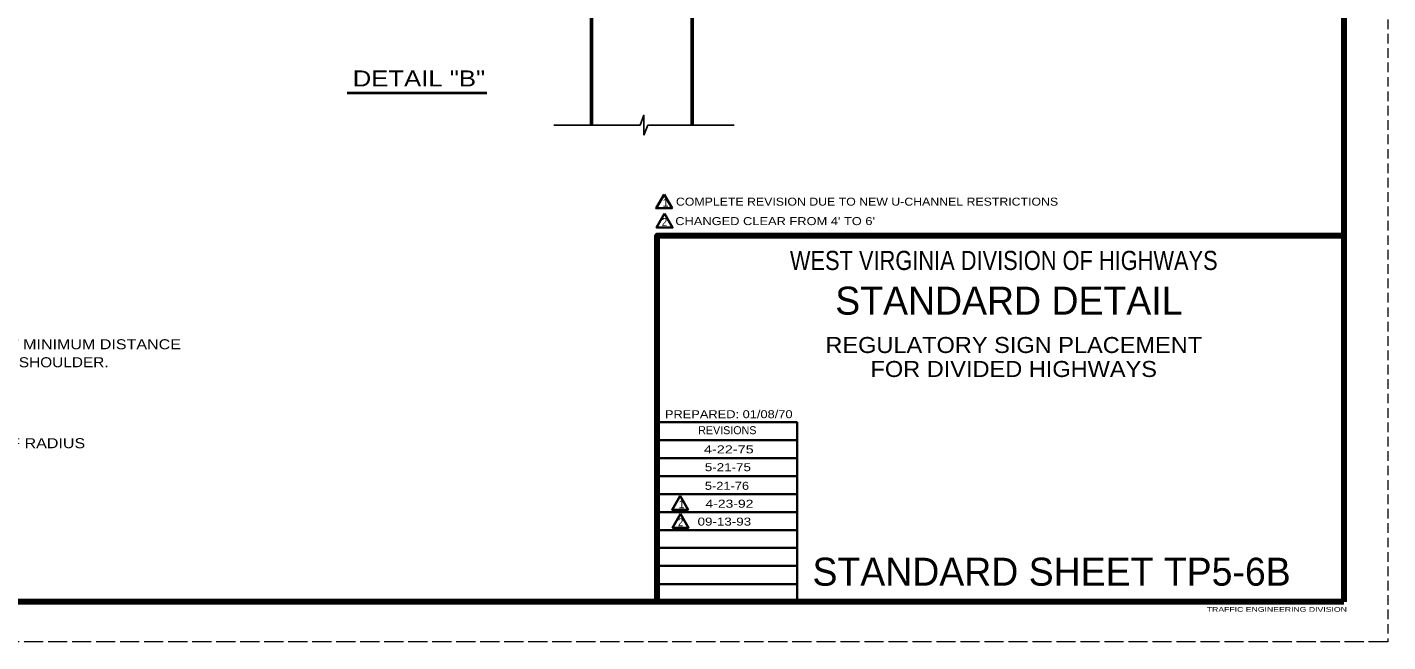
# Model space of a CAD drawing. Extents: x -133 to 547, y -328 to 112.
# Drawn here: x 206.7 to 546.7, y -328.3 to -174.6 of the extents above; entities that cross this region are included whole.
import ezdxf
from ezdxf.enums import TextEntityAlignment as Align

# ---------------------------------------------------------------- set-up
doc = ezdxf.new("R2010")
doc.units = 0
doc.header["$LTSCALE"] = 0.8
doc.linetypes.add('LONG_DASHED', pattern=[7.5, 6, -1.5])
doc.linetypes.add('MEDIUM_DASHED', pattern=[4.5, 3, -1.5])
doc.layers.add('1', color=7, linetype='Continuous', lineweight=35)
doc.layers.add('61', color=7, linetype='Continuous', lineweight=35)

msp = doc.modelspace()

# ---------------------------------------------------------------- linework, layer by layer
at = {"layer": '1', "linetype": 'MEDIUM_DASHED', "lineweight": 13}
msp.add_line((546.7136, 111.6965), (546.6936, -328.3235), dxfattribs=at)
at = {"layer": '1', "lineweight": 53}
for p, q in [((347.706, -169.145), (347.706, -199.145)), ((372.8289, -169.145), (372.8289, -199.145))]:
    msp.add_line(p, q, dxfattribs=at)
at = {"layer": '1', "lineweight": 40}
msp.add_line((286.6002, -191.0708), (321.5631, -191.0708), dxfattribs=at)
at = {"layer": '1', "lineweight": 25}
for p, q in [((338.2566, -199.1594), (359.8785, -199.1594)), ((361.7577, -199.1594), (360.8181, -201.6594)), ((361.7577, -199.1594), (383.3795, -199.1594))]:
    msp.add_line(p, q, dxfattribs=at)
at = {"layer": '1'}
for p, q in [((399.0936, -277.9035), (364.1136, -277.9035)), ((399.0936, -282.4035), (364.1136, -282.4035)), ((399.0936, -286.9035), (364.1136, -286.9035)), ((399.0936, -291.4235), (364.1136, -291.4235)), ((399.0936, -295.9035), (364.1136, -295.9035)), ((399.0936, -300.3835), (364.1136, -300.3835)), ((399.0936, -304.8835), (364.1136, -304.8835)), ((399.0936, -309.3835), (364.1136, -309.3835)), ((399.0936, -313.9035), (364.1136, -313.9035))]:
    msp.add_line(p, q, dxfattribs=at)
at = {"layer": '1', "lineweight": 25}
msp.add_lwpolyline([(360.8181, -201.6594), (360.8181, -196.6594), (359.8785, -199.1594)], dxfattribs=at)
at = {"layer": '1'}
for points in [[(365.8498, -216.4522), (363.8498, -219.9163), (367.8498, -219.9163)], [(365.9546, -221.2721), (363.9546, -224.7362), (367.9546, -224.7362)], [(369.8462, -291.8621), (367.8462, -295.3262), (371.8462, -295.3262)], [(369.9822, -296.3598), (367.9822, -299.8239), (371.9822, -299.8239)]]:
    msp.add_lwpolyline(points, close=True, dxfattribs=at)
at = {"layer": '1', "lineweight": 158}
msp.add_lwpolyline([(364.0936, -318.3435), (364.0936, -226.7635), (535.7536, -226.7635)], dxfattribs=at)
at = {"layer": '1'}
msp.add_lwpolyline([(399.0936, -318.3835), (399.0936, -273.4235), (364.1136, -273.4235)], dxfattribs=at)
at = {"layer": '61', "lineweight": 158}
for p, q in [((535.7336, 101.6965), (535.7536, -318.3435)), ((535.7536, -318.3435), (-103.3064, -318.3235))]:
    msp.add_line(p, q, dxfattribs=at)
at = {"layer": '61', "linetype": 'LONG_DASHED', "lineweight": 13}
msp.add_line((546.6936, -328.3235), (-133.3664, -328.3435), dxfattribs=at)

# ---------------------------------------------------------------- texts
at = {"layer": '1'}
for s, height, width, p in [('DETAIL "B"', 4, 1.2, (304.5717, -189.4537)), ('COMPLETE REVISION DUE TO NEW U-CHANNEL RESTRICTIONS', 2, 1.15, (416.5699, -219.2689)), ('2', 2, 0.9, (365.934, -224.3701)), ("CHANGED CLEAR FROM 4' TO 6'", 2, 1.2, (393.5924, -224.1324)), ('WEST VIRGINIA DIVISION OF HIGHWAYS', 4.795, 0.85, (450.7419, -235.3635)), ('REGULATORY SIGN PLACEMENT', 4, 1.1, (453.2325, -256.1163)), ('FOR DIVIDED HIGHWAYS', 4, 1.1, (453.2325, -262.1163)), ("- 50' FROM END OF RADIUS", 2.5, 1.2, (194.5919, -279.9243)), ('2', 2, 0.9, (369.9616, -299.4578)), ('09-13-93', 2, 1.25, (380.9029, -299.2835))]:
    msp.add_text(s, height=height, dxfattribs=dict(at, width=width)).set_placement(p, align=Align.CENTER)
for s, height, p in [('1', 2, (366.2341, -219.5284)), ('STANDARD DETAIL', 6.993, (452.0105, -246.5235)), ('1', 2, (370.2305, -294.9382))]:
    msp.add_text(s, height=height, dxfattribs=at).set_placement(p, align=Align.CENTER)
for s, height, width, p in [('ALL SIGNS ARE 6 FEET MINIMUM DISTANCE', 2.5, 1.2, (159.7242, -255.1795)), ('FROM EDGE OF PAVED SHOULDER.', 2.5, 1.15, (159.7242, -259.6795)), ('PREPARED: 01/08/70', 1.998, 1.2, (366.0536, -272.4235)), ('4-22-75', 2, 1.35, (375.8017, -281.2201)), ('5-21-75', 2, 1.25, (376.0266, -285.6718)), ('5-21-76', 2, 1.2, (376.0311, -290.332)), ('4-23-92', 2, 1.3, (376.1874, -294.8143)), ('TRAFFIC ENGINEERING DIVISION', 1.2, 1.35, (501.4736, -320.8435))]:
    msp.add_text(s, height=height, dxfattribs=dict(at, width=width)).set_placement(p)
for s, height, p in [('REVISIONS', 1.998, (374.3736, -276.4235)), ('STANDARD SHEET TP5-6B', 6.993, (402.9336, -314.3035))]:
    msp.add_text(s, height=height, dxfattribs=at).set_placement(p)

doc.saveas('drawing.dxf')
